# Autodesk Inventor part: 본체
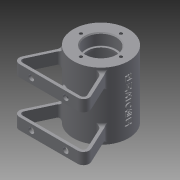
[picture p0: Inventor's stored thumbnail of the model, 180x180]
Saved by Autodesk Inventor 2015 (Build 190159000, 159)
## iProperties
Created: 2021-12
Part Number: 본체
Material: 일반
Document SubType Name: Modeling
Designer: pc-04
Density: 1 g/cm^3
Appearance: 기본값
Mass: 115.147 g
Surface Area: 363.055 cm^2
Volume: 115.147 cm^3
Author: pc-04
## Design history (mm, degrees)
sketch "스케치1"
  geometry: L1 (0, 23.783)-(0, -24.591); L2 (22.482, 0)-(-20.059, 0); L3 (16, 35)-(16, 23); L4 (16, 23)-(14, 23); L5 (14, 23)-(14, 21); L6 (14, 21)-(21, 21); L7 (21, 21)-(21, -21); L8 (21, -21)-(14, -21); L9 (14, -21)-(14, -23); L10 (14, -23)-(16, -23); L11 (16, -23)-(16, -35); L12 (16, -35)-(29, -35); L13 (29, -35)-(29, 35); L14 (29, 35)-(16, 35); 1 further point
  constraints: 28 end point, 10 perpendicular, 3 vertical, 2 point on line, 1 horizontal, 2 other
  dimensions: "d0" = 58 diameter of L13 L1; "d1" = 32 diameter of L3 L1; "d2" = 28 diameter of L5 L1; "d3" = 70 distance of L12.end L13.end; "d4" = 12 distance of L3.start L3.end; "d5" = 2 distance of L4.end L5.end; "d6" = 42 diameter of L7 L1; "d7" = 28 diameter of L9 L1; "d8" = 32 diameter of L11 L1; "d9" = 12 distance of L10.end L11.end
revolve "회전1" sketch "스케치1" stored, may be unused: angle "d10" = 90 deg
node "작업 평면1"
sketch "스케치2"
  geometry: L1 (0, 0)-(0, -60.703); L2 (-40.334, 0)-(38.661, 0); L3 (-40, -55)-(40, -55); L4 (40, -55)-(21.814, -16); L5 (-40, -55)-(-21.814, -16); L6 (-21.814, -16)-(21.814, -16); L7 (35.291, -52)-(-35.291, -52); L8 (-35.291, -52)-(-19.903, -19); L9 (-19.903, -19)-(19.903, -19); L10 (19.903, -19)-(35.291, -52)
  constraints: 20 end point, 2 horizontal, 1 point on line, 1 symmetric about line, 1 vertical, 3 other
  dimensions: "d12" = 65 deg angle of L3 L5; "d13" = 65 deg angle of L3 L4; "d14" = 39 vertical distance of L3.start L5.end; "d15" = 39 vertical distance of L3.end L4.end; "d16" = 55 distance between parallel lines of L2 L3; "d17" = 80 distance of L3.start L3.end; "d18" = 3 distance between parallel lines of L3 L7
extrude "돌출1" join sketch "스케치2" distance "d19" = 12; taper "d20" = 0 deg
fillet "모깎기1" dims "d21" = 6
fillet "모깎기2" dims "d22" = 3
fillet "모깎기3" dims "d23" = 3
sketch "스케치4"
  geometry: L1 (30.582, 11.573)-(30.582, -76.988); L2 (70.724, -30)-(-9.956, -30); C1 r 3 at (48.582, -6); C2 r 3 at (12.582, -6); C3 r 3 at (48.582, -54); C4 r 3 at (12.582, -54); 1 further point
  constraints: 4 centre point, 4 end point, 3 equal radius, 2 point on line, 2 symmetric about line, 1 horizontal, 1 horizontal alignment, 1 vertical, 1 vertical alignment
  dimensions: "d24" = 48 distance of C3.centre C1.centre; "d25" = 36 distance of C1.centre C2.centre; "d26" = 6 diameter of C2
extrude "돌출2" cut sketch "스케치4" distance "d27" = 12; taper "d28" = 0 deg
sketch "스케치5"
  geometry: L1 (0, 0)-(0, -68.401); L2 (-13.163, -18.621)-(-16.583, -28.018); L3 (-10.945, -30.07)-(-16.583, -28.018); L4 (-7.524, -20.673)-(-13.163, -18.621); L5 (0, 0)-(-22.158, -60.878); L6 (-7.524, -20.673)-(-10.945, -30.07)
  constraints: 12 end point, 2 point on line, 1 collinear, 1 perpendicular, 1 vertical
  dimensions: "d32" = 32 distance from line of L1.start L3; "d34" = 20 deg angle of L1 L5; "d35" = 6 distance between parallel lines of L5 L2; "d36" = 10 distance between parallel lines of L3 L4
revolve "회전2" sketch "스케치5" stored, may be unused: angle "d37" = 90 deg
sketch "스케치6"
  geometry: 4 further points
  constraints: 3 coincident
hole "구멍1" sketch "스케치6" at (0, 0) diameter "d38" = 4.917; stored, may be unused: countersink angle "d42" = 90 deg, drill point angle "d44" = 118 deg; dims "d39" = 16, "d40" = 4, "d41" = 2, "d43" = 21.1
fillet "모깎기4" dims "d45" = 1
sketch "스케치7" dims "d46" = 42
  geometry: L1 (0, 0)-(0, 21); 2 further points
  constraints: 2 coincident, 2 end point, 1 vertical, 1 vertical alignment, 2 other
hole "구멍2" sketch "스케치7" at (0, 21) diameter "d47" = 3.242; stored, may be unused: countersink angle "d51" = 90 deg, drill point angle "d53" = 118 deg; dims "d48" = 8, "d49" = 4, "d50" = 2, "d52" = 10
node "작업 평면2"
sketch "스케치8"
  geometry: C1 r 5 at (0, 0); 1 further point
  constraints: 1 centre point, 1 coincident
  dimensions: "d58" = 10 diameter of C1
extrude "돌출3" join sketch "스케치8" stored distance "d59" = 12; taper "d60" = 0 deg
sketch "스케치9"
  geometry: C1 r 1.5 at (0, 0); 2 further points
  constraints: 2 coincident, 1 centre point
  dimensions: "d68" = 3 diameter of C1
hole "구멍3" sketch "스케치9" diameter "d61" = 4.917; stored, may be unused: countersink angle "d65" = 90 deg, drill point angle "d67" = 118 deg; dims "d62" = 6, "d63" = 4, "d64" = 2, "d66" = 8
extrude "돌출4" cut sketch "스케치9" distance "d69" = 20; taper "d70" = 0 deg
fillet "모깎기5" dims "d71" = 0.3
fillet "모깎기6" dims "d72" = 3
chamfer "모따기1" distance "d73" = 1; stored, may be unused: second distance "d74" = 2, angle "d75" = 45 deg
fillet "모깎기7" dims "d76" = 1
node "작업 평면3"
sketch "스케치10"
  geometry: L1 (18.759, 8.024)-(18.759, -7.807); L2 (18.759, -7.807)-(-19.626, -7.807); L3 (-19.626, -7.807)-(-19.626, 8.024); L4 (-19.626, 8.024)-(18.759, 8.024); 1 further point
  constraints: 2 other
extrude "돌출5" join sketch "스케치10" stored distance "d78" = 20; taper "d79" = 0 deg
fillet "모깎기8" dims "d80" = 3
node "솔리드1"
mirror "대칭1"
mirror "대칭2"
pattern_circular "원형 패턴1" dims angle "d55" = 360 deg
mirror "대칭3"
other parameters: "d57" = 32
